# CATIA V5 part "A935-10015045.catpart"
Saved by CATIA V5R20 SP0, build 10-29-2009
Part number: A935-10015045
Source: Unknown
Property "A": "60.000"
Property "ARTICLENO": "A935-10015045"
Property "B": "30.000"
Property "BOMINFO": "A935-10015045"
Property "CODE": "A935-10015045"
Property "L": "150.000"
Property "L1": "127.860"
Property "LINA": "A935-10015045"
Property "NB": "A935-10015045"
Property "NBSYN": "$CODE."
Property "NN": "A935"
Property "NT": "VDI 3357 H-Type Cam Drivers, steel (16MnCr5)"
Property "SUPPLIER": "CF"
Property "T": "45.000"
Property "W": "100.000"
Bounding box of the stored display mesh (mm): x 0 to 150, y 0 to 45, z -100 to 0
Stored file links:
  C:\Users\Utente\Desktop\3D files A935\A935-10015045.catpart
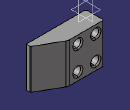
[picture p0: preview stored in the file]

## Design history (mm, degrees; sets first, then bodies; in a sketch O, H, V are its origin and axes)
Body1 "Geometry.1" (main body)
  Solid1 "A935-10015045.catpart": solid without history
